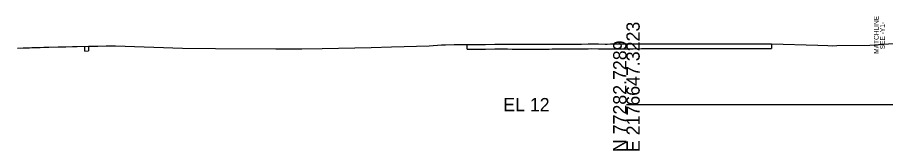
# Model space of a CAD drawing. Extents: x 2203888 to 2204323, y 61398 to 65948.
# Drawn here: x 2203920 to 2204103.3, y 63897.6 to 63925.7 of the extents above; entities that cross this region are included whole.
import ezdxf

# ---------------------------------------------------------------- set-up
doc = ezdxf.new("R2010")
doc.units = 0
for name, color, linetype in [('Exist Plan Preparation Drainage Flow Arrows', 7, 'Continuous'), ('Prop Drainage Structure Pipe RCP 60in Class IV', 7, 'Continuous'), ('Prop Earthen Structure Base Ditch Special Lateral Detail Label', 7, 'Continuous'), ('Prop Plan Preparation Crest', 7, 'Continuous'), ('Prop SS Transition Line', 7, 'Continuous')]:
    doc.layers.add(name, color=color, linetype=linetype)

msp = doc.modelspace()

# ---------------------------------------------------------------- linework, layer by layer
at = {"layer": 'Exist Plan Preparation Drainage Flow Arrows'}
msp.add_line((2204048.57, 63907.31), (2204120, 63907.31), dxfattribs=at)
at = {"layer": 'Prop Drainage Structure Pipe RCP 60in Class IV'}
for p, q in [((2203934.27, 63918.61), (2203934.27, 63919.61)), ((2203934.27, 63918.61), (2203935, 63918.63)), ((2203935, 63919.63), (2203935, 63918.63)), ((2203935, 63918.63), (2203935, 63918.63)), ((2204014.98, 63918.99), (2204014.98, 63919.99)), ((2204014.98, 63918.99), (2204015.59, 63919)), ((2204015.59, 63919), (2204016.83, 63919)), ((2204016.83, 63919), (2204017.68, 63919)), ((2204017.68, 63919), (2204018.82, 63919.02)), ((2204018.82, 63919.02), (2204020.78, 63919.05)), ((2204020.78, 63919.05), (2204021.2, 63919.05)), ((2204021.2, 63919.05), (2204022.61, 63919.05)), ((2204022.61, 63919.05), (2204023.47, 63919.05)), ((2204023.47, 63919.05), (2204024.44, 63919.04)), ((2204024.44, 63919.04), (2204026.44, 63919.04)), ((2204026.44, 63919.04), (2204028.09, 63919.04)), ((2204028.09, 63919.04), (2204029.35, 63919.03)), ((2204029.35, 63919.03), (2204029.9, 63919.03)), ((2204029.9, 63919.03), (2204030.82, 63919.04)), ((2204030.82, 63919.04), (2204031.72, 63919.04)), ((2204031.72, 63919.04), (2204032.26, 63919.04)), ((2204032.26, 63919.04), (2204032.88, 63919.05)), ((2204032.88, 63919.05), (2204033.72, 63919.06)), ((2204033.72, 63919.06), (2204034.58, 63919.07)), ((2204034.58, 63919.07), (2204035.62, 63919.07)), ((2204035.62, 63919.07), (2204037.22, 63919.08)), ((2204037.22, 63919.08), (2204038.22, 63919.09)), ((2204038.22, 63919.09), (2204039.06, 63919.09)), ((2204039.06, 63919.09), (2204040.49, 63919.11)), ((2204040.49, 63919.11), (2204041.14, 63919.12)), ((2204041.14, 63919.12), (2204042.71, 63919.11)), ((2204042.71, 63919.11), (2204044.08, 63919.09)), ((2204044.08, 63919.09), (2204044.52, 63919.09)), ((2204044.52, 63919.09), (2204045.2, 63919.1)), ((2204045.2, 63919.1), (2204046.34, 63919.1)), ((2204046.34, 63919.1), (2204047.06, 63919.1)), ((2204047.06, 63919.1), (2204047.49, 63919.11)), ((2204047.49, 63919.11), (2204047.93, 63919.11)), ((2204047.93, 63919.11), (2204048.73, 63919.11)), ((2204048.73, 63919.11), (2204050.02, 63919.11)), ((2204050.02, 63919.11), (2204051.74, 63919.12)), ((2204051.74, 63919.12), (2204052.98, 63919.12)), ((2204052.98, 63919.12), (2204053.49, 63919.12)), ((2204053.49, 63919.12), (2204054.22, 63919.13)), ((2204054.22, 63919.13), (2204055.28, 63919.13)), ((2204055.28, 63919.13), (2204055.95, 63919.14)), ((2204055.95, 63919.14), (2204058.92, 63919.13)), ((2204058.92, 63919.13), (2204060.26, 63919.14)), ((2204060.26, 63919.14), (2204060.75, 63919.14)), ((2204060.75, 63919.14), (2204061.82, 63919.15)), ((2204061.82, 63919.15), (2204063.76, 63919.15)), ((2204063.76, 63919.15), (2204064.9, 63919.15)), ((2204064.9, 63919.15), (2204067.92, 63919.16)), ((2204067.92, 63919.16), (2204069.61, 63919.16)), ((2204069.61, 63919.16), (2204070.93, 63919.16)), ((2204070.93, 63919.16), (2204071.29, 63919.16)), ((2204071.29, 63919.16), (2204071.73, 63919.16)), ((2204071.73, 63919.16), (2204073.05, 63919.16)), ((2204073.05, 63919.16), (2204073.95, 63919.15)), ((2204073.95, 63919.15), (2204074.85, 63919.15)), ((2204074.85, 63919.15), (2204076.17, 63919.15)), ((2204076.17, 63919.15), (2204076.65, 63919.15)), ((2204076.65, 63919.15), (2204077.1, 63919.15)), ((2204077.1, 63919.15), (2204077.58, 63919.15)), ((2204077.58, 63919.15), (2204079.22, 63919.14)), ((2204079.22, 63920.14), (2204079.22, 63919.14))]:
    msp.add_line(p, q, dxfattribs=at)
at = {"layer": 'Prop Plan Preparation Crest'}
msp.add_lwpolyline([(2203920, 63919.24), (2203921.23, 63919.28), (2203922.54, 63919.32), (2203923.03, 63919.33), (2203923.74, 63919.35), (2203924.83, 63919.38), (2203925.57, 63919.4), (2203926.62, 63919.43), (2203928.6, 63919.48), (2203930.23, 63919.52), (2203931.66, 63919.55), (2203932.05, 63919.56), (2203932.6, 63919.57), (2203935, 63919.63), (2203935.31, 63919.64), (2203937.02, 63919.67), (2203938.74, 63919.69), (2203940.39, 63919.72), (2203940.71, 63919.72), (2203954.86, 63919.22), (2203961.85, 63919.14), (2203974.54, 63919.08), (2203980.07, 63919.09), (2203984.31, 63919.16), (2203994.67, 63919.33), (2203998.99, 63919.49), (2204006.9, 63919.73), (2204009.52, 63919.92), (2204010.37, 63919.93), (2204012.23, 63919.97), (2204012.94, 63919.98), (2204014.07, 63919.99), (2204014.54, 63919.99), (2204014.93, 63919.99), (2204015.59, 63920), (2204016.83, 63920), (2204017.68, 63920), (2204018.82, 63920.02), (2204020.78, 63920.05), (2204021.2, 63920.05), (2204022.61, 63920.05), (2204023.47, 63920.05), (2204024.44, 63920.04), (2204026.44, 63920.04), (2204028.09, 63920.04), (2204029.35, 63920.03), (2204029.9, 63920.03), (2204030.82, 63920.04), (2204031.72, 63920.04), (2204032.26, 63920.04), (2204032.88, 63920.05), (2204033.72, 63920.06), (2204034.58, 63920.07), (2204035.62, 63920.07), (2204037.22, 63920.08), (2204038.22, 63920.09), (2204039.06, 63920.09), (2204040.49, 63920.11), (2204041.14, 63920.12), (2204042.71, 63920.11), (2204044.08, 63920.09), (2204044.52, 63920.09), (2204045.2, 63920.1), (2204046.34, 63920.1), (2204047.06, 63920.1), (2204047.49, 63920.11), (2204047.93, 63920.11), (2204048.73, 63920.11), (2204050.02, 63920.11), (2204051.74, 63920.12), (2204052.98, 63920.12), (2204053.49, 63920.12), (2204054.22, 63920.13), (2204055.28, 63920.13), (2204055.95, 63920.14), (2204058.92, 63920.13), (2204060.26, 63920.14), (2204060.75, 63920.14), (2204061.82, 63920.15), (2204063.76, 63920.15), (2204064.9, 63920.15), (2204067.92, 63920.16), (2204069.61, 63920.16), (2204070.93, 63920.16), (2204071.29, 63920.16), (2204071.73, 63920.16), (2204073.05, 63920.16), (2204073.95, 63920.15), (2204074.85, 63920.15), (2204076.17, 63920.15), (2204076.65, 63920.15), (2204077.1, 63920.15), (2204077.58, 63920.15), (2204079.22, 63920.14), (2204088.97, 63919.84), (2204091.05, 63919.77), (2204092.05, 63919.71), (2204092.96, 63919.75), (2204099.92, 63919.86), (2204106.82, 63920.32)], dxfattribs=at)

# ---------------------------------------------------------------- texts
at = {"layer": 'Exist Plan Preparation Drainage Flow Arrows'}
for s, p in [('E 2176647.3223', (2204051.37, 63897.31)), ('N 77282.7289', (2204048.57, 63897.31))]:
    msp.add_text(s, height=2.8, rotation=90, dxfattribs=at).set_placement(p)
msp.add_text('EL 12', height=2.8, dxfattribs=at).set_placement((2204022.57, 63905.91))
at = {"layer": 'Prop Earthen Structure Base Ditch Special Lateral Detail Label'}
msp.add_text('-', height=0.0001, dxfattribs=at).set_placement((2204048.57, 63907.31))
at = {"layer": 'Prop SS Transition Line'}
for s, p in [('MATCHLINE', (2204101.82, 63918.04)), ('SEE -Y1- ', (2204103.13, 63919))]:
    msp.add_text(s, height=1, rotation=90, dxfattribs=at).set_placement(p)

doc.saveas('drawing.dxf')
